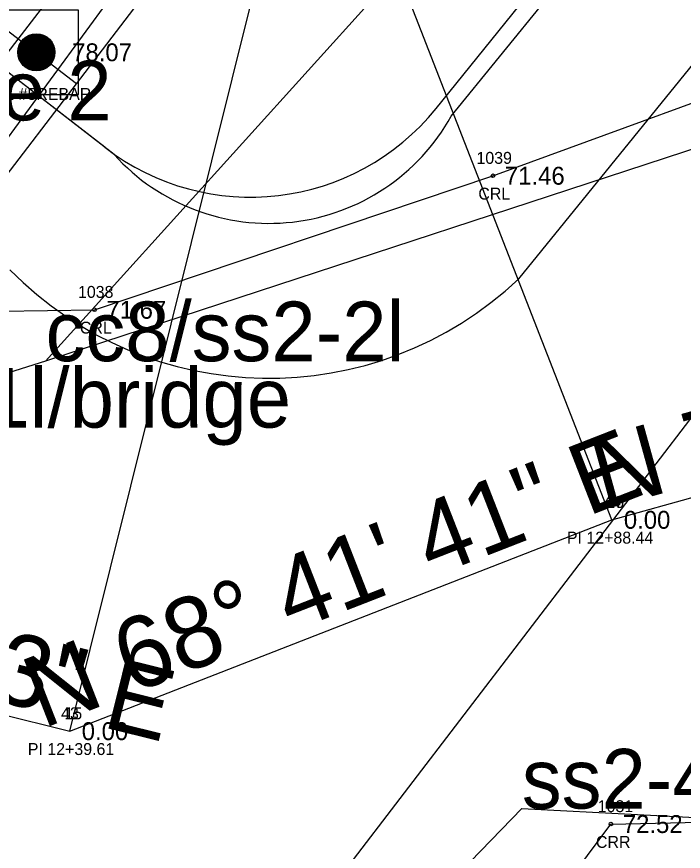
# Model space of a CAD drawing. Extents: x 2500794 to 2511032, y 910653 to 917533.
# Drawn here: x 2505841.9 to 2505897.8, y 913471.7 to 913541.8 of the extents above; entities that cross this region are included whole.
import ezdxf

# ---------------------------------------------------------------- set-up
doc = ezdxf.new("R2010")
doc.units = 0
for name, color, linetype in [('Default', 7, 'Continuous'), ('RD_EX_H2O', 7, 'Continuous'), ('RD_EX_H2O_txCode', 7, 'Continuous'), ('RD_EX_H2O_WetLd', 7, 'Continuous'), ('RD_EX_Road', 7, 'Continuous'), ('RD_EX_RW', 7, 'Continuous'), ('RD_EX_TX_H2O_ELEV', 7, 'Continuous'), ('RD_HC_Cl', 7, 'Continuous'), ('RD_HC_Data', 7, 'Continuous'), ('RD_HC_Survey', 7, 'Continuous'), ('RD_HC_Survey_ELEV', 7, 'Continuous'), ('RD_HC_Survey_txCode', 7, 'Continuous'), ('RD_HC_txCode', 7, 'Continuous'), ('RD_PD_Bridge', 7, 'Continuous'), ('RD_PD_CstnLmt', 7, 'Continuous'), ('RD_PD_Signals', 7, 'Continuous'), ('RD_Sketch9', 7, 'Continuous'), ('RD_SMD_Locator', 7, 'Continuous'), ('RD_XS_NPDES', 7, 'Continuous')]:
    doc.layers.add(name, color=color, linetype=linetype)

# ---------------------------------------------------------------- blocks, each defined once
blk = doc.blocks.new('POINT_DISPLAY')
at = {"layer": 'Default'}
blk.add_line((0, 0), (0, 0), dxfattribs=at)
blk = doc.blocks.new('Non-Wetland Waters (Tributaries)')
at = {"layer": 'Default'}
for points in [[(636523.855, 232037.448), (636501.371, 232037.816), (636484.456, 232032.271), (636479.967, 232030.855)], [(636470.177, 232019.736), (636472.749, 232019.524), (636488.229, 232016.145), (636494.608, 232022.734), (636511.865, 232021.84)]]:
    blk.add_lwpolyline(points, dxfattribs=at)
blk = doc.blocks.new('Wetlands')
at = {"layer": 'Default'}
for points in [[(636578.378, 232108.026), (636523.855, 232037.448), (636501.371, 232037.816), (636484.456, 232032.271), (636499.849, 232049.322), (636504.147, 232059.556), (636518.345, 232075.791), (636532.382, 232092.673), (636539.146, 232087.393), (636544.708, 232099.914), (636554.736, 232107.733), (636570.529, 232108.061), (636578.378, 232108.026)], [(636454.761, 231993.951), (636472.749, 232019.524), (636488.229, 232016.145), (636494.608, 232022.734), (636511.865, 232021.84), (636504.627, 232012.418), (636482.687, 231983.857)]]:
    blk.add_lwpolyline(points, dxfattribs=at)

msp = doc.modelspace()

# ---------------------------------------------------------------- linework, layer by layer
at = {"layer": 'RD_EX_H2O_txCode'}
for points in [[(2505762.262, 913658.109), (2505746.145, 913644.246), (2505726.467, 913615.205), (2505674.206, 913628.007), (2505666.247, 913620.583), (2505714.598, 913592.147), (2505793.902, 913560.447), (2505801.323, 913552.799), (2505803.704, 913539.769), (2505832.625, 913516.964), (2505848.424, 913517.193), (2505881.862, 913528.443), (2505910.198, 913538.779), (2505939.304, 913544.448), (2505946.254, 913542.537), (2505974.653, 913535.178), (2506004.111, 913524.704), (2506052.031, 913515.471), (2506115.491, 913494.68), (2506138.045, 913548.886)], [(2505789.475, 913464.314), (2505795.694, 913463.103), (2505812.13, 913464.368), (2505832.031, 913446.726), (2505876.169, 913453.079), (2505891.756, 913474.027), (2505941.737, 913475.129), (2505995.42, 913465.054), (2506040.13, 913447.397), (2506076.302, 913432.472), (2506096.958, 913385.48)]]:
    msp.add_lwpolyline(points, dxfattribs=at)
at = {"layer": 'RD_EX_Road'}
msp.add_lwpolyline([(2506040.709, 913800.235), (2505979.729, 913720.468), (2505920.444, 913642.615), (2505859.425, 913562.605), (2505835.441, 913531.43), (2505833.766, 913527.251)], dxfattribs=at)
at = {"layer": 'RD_EX_RW'}
msp.add_line((2505867.15, 913467.138), (2505934.138, 913554.757), dxfattribs=at)
at = {"layer": 'RD_HC_Cl'}
for p, q in [((2505891.844, 913499.564), (2505947.94, 913515.141)), ((2505846.35, 913481.822), (2505891.844, 913499.564)), ((2505811.027, 913490.61), (2505846.35, 913481.822))]:
    msp.add_line(p, q, dxfattribs=at)
at = {"layer": 'RD_HC_Data'}
for p, q in [((2505891.844, 913499.564), (2505849.734, 913607.543)), ((2505846.35, 913481.822), (2505874.191, 913593.725)), ((2505811.027, 913490.61), (2505879.278, 913583.557))]:
    msp.add_line(p, q, dxfattribs=at)
at = {"layer": 'RD_HC_Survey'}
for p, q in [((2505842.536, 913537.625), (2505842.536, 913539.985)), ((2505842.586, 913537.584), (2505842.586, 913540.026)), ((2505842.636, 913537.546), (2505842.636, 913540.064)), ((2505842.686, 913537.511), (2505842.686, 913540.099)), ((2505842.736, 913537.479), (2505842.736, 913540.131)), ((2505842.786, 913537.45), (2505842.786, 913540.16)), ((2505842.836, 913537.423), (2505842.836, 913540.187)), ((2505842.886, 913537.399), (2505842.886, 913540.212)), ((2505842.936, 913537.376), (2505842.936, 913540.234)), ((2505842.986, 913537.356), (2505842.986, 913540.255)), ((2505843.036, 913537.337), (2505843.036, 913540.273)), ((2505843.086, 913537.321), (2505843.086, 913540.29)), ((2505843.136, 913537.306), (2505843.136, 913540.304)), ((2505843.186, 913537.293), (2505843.186, 913540.317)), ((2505843.236, 913537.282), (2505843.236, 913540.328)), ((2505843.286, 913537.273), (2505843.286, 913540.338)), ((2505843.336, 913537.265), (2505843.336, 913540.345)), ((2505843.386, 913537.259), (2505843.386, 913540.351)), ((2505843.436, 913537.255), (2505843.436, 913540.356)), ((2505843.486, 913537.252), (2505843.486, 913540.359)), ((2505843.536, 913537.251), (2505843.536, 913540.36)), ((2505843.586, 913537.251), (2505843.586, 913540.359)), ((2505843.636, 913537.253), (2505843.636, 913540.357)), ((2505843.686, 913537.257), (2505843.686, 913540.354)), ((2505843.736, 913537.262), (2505843.736, 913540.348)), ((2505843.786, 913537.269), (2505843.786, 913540.341)), ((2505843.836, 913537.278), (2505843.836, 913540.333)), ((2505843.886, 913537.288), (2505843.886, 913540.323)), ((2505843.936, 913537.3), (2505843.936, 913540.311)), ((2505843.986, 913537.314), (2505843.986, 913540.297)), ((2505844.036, 913537.329), (2505844.036, 913540.281)), ((2505844.086, 913537.347), (2505844.086, 913540.264)), ((2505844.136, 913537.366), (2505844.136, 913540.244)), ((2505844.186, 913537.388), (2505844.186, 913540.223)), ((2505844.236, 913537.411), (2505844.236, 913540.199)), ((2505844.286, 913537.437), (2505844.286, 913540.173)), ((2505844.336, 913537.465), (2505844.336, 913540.145)), ((2505844.386, 913537.496), (2505844.386, 913540.115)), ((2505844.436, 913537.529), (2505844.436, 913540.081)), ((2505844.486, 913537.566), (2505844.486, 913540.045)), ((2505844.536, 913537.605), (2505844.536, 913540.005)), ((2505842.086, 913538.276), (2505842.086, 913539.334)), ((2505842.136, 913538.155), (2505842.136, 913539.456)), ((2505842.186, 913538.056), (2505842.186, 913539.555)), ((2505842.236, 913537.971), (2505842.236, 913539.639)), ((2505842.286, 913537.897), (2505842.286, 913539.713)), ((2505842.336, 913537.832), (2505842.336, 913539.779)), ((2505842.386, 913537.772), (2505842.386, 913539.838)), ((2505842.436, 913537.719), (2505842.436, 913539.892)), ((2505842.486, 913537.67), (2505842.486, 913539.941)), ((2505844.586, 913537.648), (2505844.586, 913539.962)), ((2505844.636, 913537.695), (2505844.636, 913539.916)), ((2505844.686, 913537.746), (2505844.686, 913539.864)), ((2505844.736, 913537.803), (2505844.736, 913539.808)), ((2505844.786, 913537.865), (2505844.786, 913539.745)), ((2505844.836, 913537.935), (2505844.836, 913539.676)), ((2505844.886, 913538.014), (2505844.886, 913539.597)), ((2505844.936, 913538.105), (2505844.936, 913539.505)), ((2505844.986, 913538.215), (2505844.986, 913539.396)), ((2505842.036, 913538.443), (2505842.036, 913539.167)), ((2505845.036, 913538.355), (2505845.036, 913539.255)), ((2505845.086, 913538.579), (2505845.086, 913539.031))]:
    msp.add_line(p, q, dxfattribs=at)
msp.add_lwpolyline([(2505847.083, 913542.341), (2505840.012, 913542.341), (2505840.012, 913535.27), (2505847.083, 913535.27)], close=True, dxfattribs=at)
msp.add_circle((2505843.548, 913538.805), 1.555, dxfattribs=at)
at = {"layer": 'RD_PD_Bridge'}
for p, q in [((2505846.919, 913536.17), (2505819.908, 913556.821)), ((2505846.919, 913536.17), (2505859.066, 913552.059)), ((2505821.073, 913502.365), (2505846.919, 913536.17))]:
    msp.add_line(p, q, dxfattribs=at)
at = {"layer": 'RD_PD_CstnLmt'}
for p, q in [((2505878.362, 913533.443), (2505897.774, 913557.383)), ((2505850.072, 913530.219), (2505816.894, 913555.889))]:
    msp.add_line(p, q, dxfattribs=at)
msp.add_arc((2505863.063, 913541.954), 17.507, 222.09102, 330.91269, dxfattribs=at)
at = {"layer": 'RD_PD_Signals'}
for p, q in [((2505877.094, 913534.098), (2505896.589, 913558.289)), ((2505849.283, 913530.829), (2505817.814, 913555.178))]:
    msp.add_line(p, q, dxfattribs=at)
msp.add_arc((2505861.522, 913546.648), 20, 232.27049, 321.13636, dxfattribs=at)
at = {"layer": 'RD_Sketch9'}
msp.add_arc((2504883.086, 914369.786), 1375, 311.510647, 322.600707, dxfattribs=at)
at = {"layer": 'RD_SMD_Locator'}
for centre in [(2505843.548, 913538.805), (2505881.862, 913528.443), (2505848.424, 913517.193), (2505891.756, 913474.027)]:
    msp.add_circle(centre, 0.15, dxfattribs=at)
at = {"layer": 'RD_XS_NPDES'}
msp.add_line((2505884.036, 913519.799), (2505907.872, 913549.195), dxfattribs=at)
msp.add_arc((2505863.063, 913541.954), 30.507, 224.56345, 313.42932, dxfattribs=at)

# ---------------------------------------------------------------- block references
at = {"layer": 'Default', "xscale": 3.937007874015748, "yscale": 3.937007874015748}
for name, p in [('Wetlands', (0, 0)), ('Non-Wetland Waters (Tributaries)', (0, 0)), ('POINT_DISPLAY', (2505844.316, 913512.878)), ('POINT_DISPLAY', (2505844.316, 913512.878)), ('POINT_DISPLAY', (2505884.283, 913475.33)), ('POINT_DISPLAY', (2505884.283, 913475.33))]:
    msp.add_blockref(name, p, dxfattribs=at)
at = {"layer": 'RD_EX_H2O', "xscale": 3.937007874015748, "yscale": 3.937007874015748}
msp.add_blockref('Non-Wetland Waters (Tributaries)', (0, 0), dxfattribs=at)
at = {"layer": 'RD_EX_H2O_WetLd', "xscale": 3.937007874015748, "yscale": 3.937007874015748}
msp.add_blockref('Wetlands', (0, 0), dxfattribs=at)

# ---------------------------------------------------------------- texts
at = {"layer": 'Default'}
for s, p in [('cl/bridge 2', (2505819.016, 913533.093)), ('cl/bridge 2', (2505819.016, 913533.093)), ('cc8/ss2-2l', (2505844.316, 913512.878)), ('cc8/ss2-2l', (2505844.316, 913512.878)), ('ss2-1l/bridge', (2505826.643, 913507.303)), ('ss2-1l/bridge', (2505826.643, 913507.303)), ('ss2-4r', (2505884.283, 913475.33)), ('ss2-4r', (2505884.283, 913475.33))]:
    msp.add_text(s, height=5, dxfattribs=at).set_placement(p)
at = {"layer": 'RD_EX_H2O_txCode'}
for s, p in [('1039', (2505880.476, 913529.443)), ('CRL', (2505880.634, 913526.443)), ('1038', (2505847.038, 913518.193)), ('CRL', (2505847.195, 913515.193)), ('1031', (2505890.653, 913475.027)), ('CRR', (2505890.504, 913472.027))]:
    msp.add_text(s, height=1, dxfattribs=at).set_placement(p)
at = {"layer": 'RD_EX_TX_H2O_ELEV'}
for s, p in [('71.46', (2505882.862, 913527.693)), ('71.67', (2505849.424, 913516.443)), ('72.52', (2505892.756, 913473.277))]:
    msp.add_text(s, height=1.5, dxfattribs=at).set_placement(p)
at = {"layer": 'RD_HC_Data'}
for s, rotation, p in [('N 74%%d 28\' 52" E', 15.51899, (2505891.151, 913500.409)), ('N 68%%d 41\' 41" E', 21.30518, (2505844.063, 913482.004)), ('S 76%%d 01\' 43" E', 346.02866, (2505801.766, 913493.945))]:
    msp.add_text(s, height=6, rotation=rotation, dxfattribs=at).set_placement(p)
at = {"layer": 'RD_HC_Survey_ELEV'}
for s, p in [('78.07', (2505846.548, 913538.055)), ('0.00', (2505892.844, 913498.814)), ('0.00', (2505892.844, 913498.814)), ('0.00', (2505847.35, 913481.072)), ('0.00', (2505847.35, 913481.072))]:
    msp.add_text(s, height=1.5, dxfattribs=at).set_placement(p)
at = {"layer": 'RD_HC_Survey_txCode'}
msp.add_text('CP 1 #5REBAR', height=1, dxfattribs=at).set_placement((2505838.713, 913534.805))
at = {"layer": 'RD_HC_txCode'}
for s, p in [('44', (2505891.112, 913500.564)), ('16', (2505891.372, 913500.564)), ('PI 12+88.44', (2505888.065, 913497.564)), ('PI 12+88.44', (2505888.065, 913497.564)), ('43', (2505845.618, 913482.822)), ('15', (2505845.901, 913482.822)), ('PI 12+39.61', (2505842.83, 913479.822)), ('PI 12+39.61', (2505842.83, 913479.822))]:
    msp.add_text(s, height=1, dxfattribs=at).set_placement(p)

doc.saveas('drawing.dxf')
